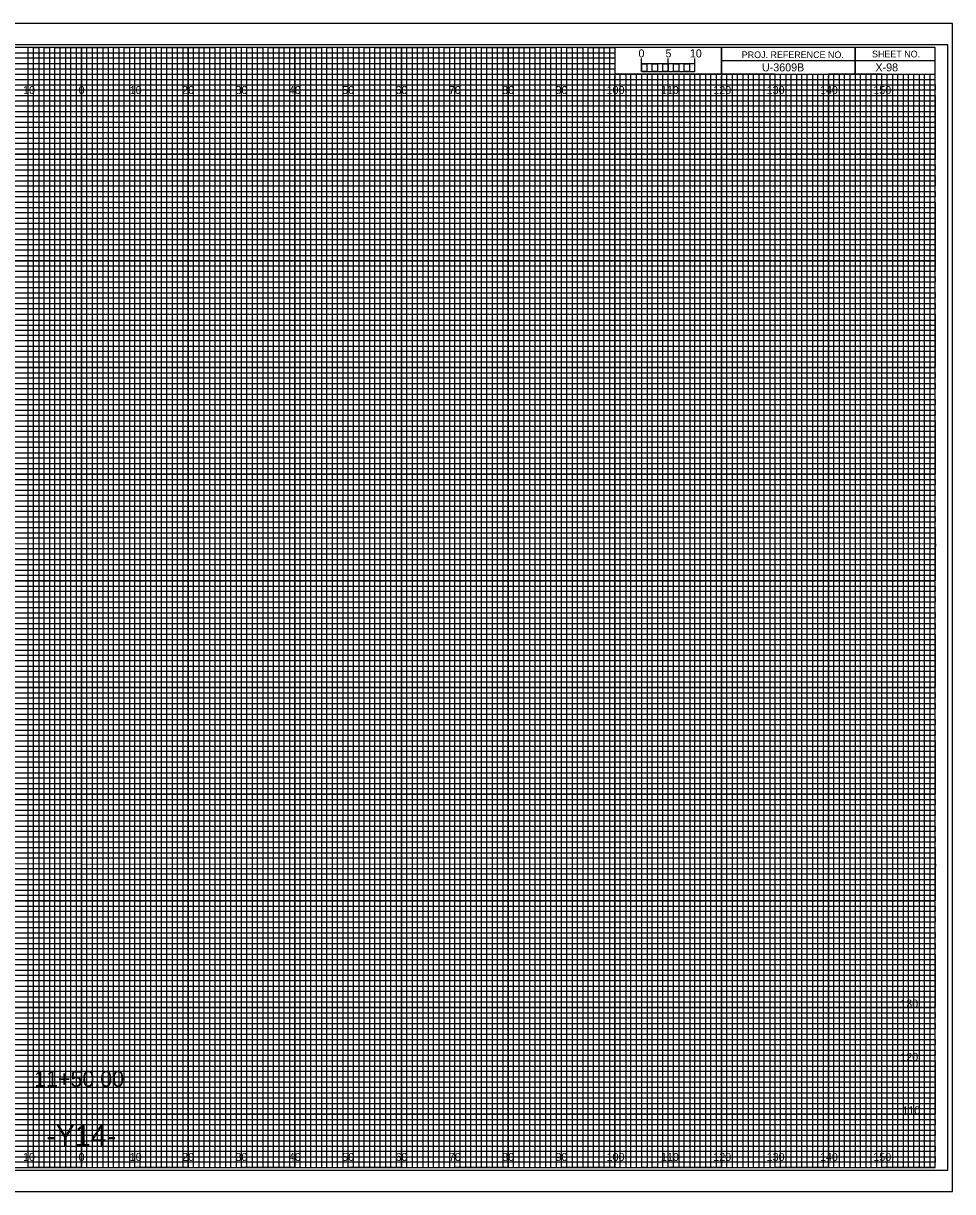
# Model space of a CAD drawing. Extents: x -13 to 323, y -5 to 434.
# Drawn here: x 149.1 to 323.3, y 215.5 to 434.5 of the extents above; entities that cross this region are included whole.
import ezdxf

# ---------------------------------------------------------------- set-up
doc = ezdxf.new("R2010")
doc.units = 0
for name, color, linetype in [('Prop XS Alignment Label', 7, 'Continuous'), ('Prop XS Bar Scale Labels', 7, 'Continuous'), ('Prop XS Elevation Labels', 7, 'Continuous'), ('Prop XS Offset Labels', 7, 'Continuous'), ('Prop XS Project Number', 7, 'Continuous'), ('Prop XS Sheet Number', 7, 'Continuous'), ('Prop XS Station Labels', 7, 'Continuous'), ('Sheet Cross Section CELL', 7, 'Continuous'), ('Sheet Cross Section Grid Major CELL', 7, 'Continuous'), ('Sheet Cross Section Grid Middle CELL', 7, 'Continuous'), ('Sheet Cross Section Grid Minor 1 CELL', 7, 'Continuous'), ('Sheet Cross Section Grid Minor 2 CELL', 7, 'Continuous'), ('Sheet Cross Section Scale CELL', 7, 'Continuous'), ('Sheet Cutting Line CELL', 7, 'Continuous'), ('Sheet DOT Grid CELL', 7, 'Continuous'), ('Sheet Plot Border Inside CELL', 7, 'Continuous'), ('Sheet Plot Border Outside CELL', 7, 'Continuous')]:
    doc.layers.add(name, color=color, linetype=linetype)

msp = doc.modelspace()

# ---------------------------------------------------------------- linework, layer by layer
at = {"layer": 'Sheet Cross Section CELL'}
for p, q in [((305, 430), (305, 425)), ((305, 425), (305, 430)), ((280, 427.5), (280, 425)), ((320, 427.49), (280, 427.49)), ((280, 425), (320, 425))]:
    msp.add_line(p, q, dxfattribs=at)
for points in [[(320, 430), (0, 430), (0, 220), (320, 220)], [(280, 430), (260, 430), (260, 425.03), (280, 425.03)], [(320, 430), (280, 430), (280, 425), (320, 425)]]:
    msp.add_lwpolyline(points, close=True, dxfattribs=at)
at = {"layer": 'Sheet Cross Section Grid Major CELL'}
for p, q in [((150, 430), (140, 430)), ((150, 220), (150, 430)), ((170, 430), (160, 430)), ((160, 430), (160, 220)), ((170, 220), (170, 430)), ((190, 430), (180, 430)), ((180, 430), (180, 220)), ((190, 220), (190, 430)), ((210, 430), (200, 430)), ((200, 430), (200, 220)), ((210, 220), (210, 430)), ((230, 430), (220, 430)), ((220, 430), (220, 220)), ((230, 220), (230, 430)), ((250, 430), (240, 430)), ((240, 430), (240, 220)), ((250, 220), (250, 430)), ((260, 430), (260, 220)), ((270, 220), (270, 425)), ((290, 425), (280, 425)), ((280, 425), (280, 220)), ((290, 220), (290, 425)), ((310, 425), (300, 425)), ((300, 425), (300, 220)), ((310, 220), (310, 425)), ((160, 220), (150, 220)), ((180, 220), (170, 220)), ((200, 220), (190, 220)), ((220, 220), (210, 220)), ((240, 220), (230, 220)), ((260, 220), (250, 220)), ((280, 220), (270, 220)), ((300, 220), (290, 220)), ((320, 220), (310, 220)), ((320, 220), (320, 220))]:
    msp.add_line(p, q, dxfattribs=at)
for points in [[(0, 420), (320, 420), (320, 410), (0, 410)], [(0, 400), (320, 400), (320, 390), (0, 390)], [(0, 380), (320, 380), (320, 370), (0, 370)], [(0, 360), (320, 360), (320, 350), (0, 350)], [(0, 340), (320, 340), (320, 330), (0, 330)], [(0, 320), (320, 320), (320, 310), (0, 310)], [(0, 300), (320, 300), (320, 290), (0, 290)], [(0, 280), (320, 280), (320, 270), (0, 270)], [(0, 260), (320, 260), (320, 250), (0, 250)], [(0, 240), (320, 240), (320, 230), (0, 230)]]:
    msp.add_lwpolyline(points, dxfattribs=at)
at = {"layer": 'Sheet Cross Section Grid Middle CELL'}
for points in [[(145, 220), (155, 220), (155, 430), (165, 430), (165, 220), (175, 220), (175, 430), (185, 430), (185, 220), (195, 220), (195, 430), (205, 430), (205, 220), (215, 220), (215, 430), (225, 430), (225, 220), (235, 220), (235, 430), (245, 430), (245, 220), (255, 220), (255, 430), (259.93, 430), (260, 430), (260, 425), (264.99, 425), (264.99, 220), (275, 220), (275, 425), (285, 425), (285, 220), (295, 220), (295, 425), (305, 425), (305, 220), (315, 220), (315, 425)], [(0, 425), (275, 425)], [(0, 405), (320, 405), (320, 415), (0, 415)], [(0, 385), (320, 385), (320, 395), (0, 395)], [(0, 365), (320, 365), (320, 375), (0, 375)], [(0, 345), (320, 345), (320, 355), (0, 355)], [(0, 325), (320, 325), (320, 335), (0, 335)], [(0, 305), (320, 305), (320, 315), (0, 315)], [(0, 285), (320, 285), (320, 295), (0, 295)], [(0, 265), (320, 265), (320, 275), (0, 275)], [(0, 245), (320, 245), (320, 255), (0, 255)], [(0, 225), (320, 225), (320, 235), (0, 235)]]:
    msp.add_lwpolyline(points, dxfattribs=at)
at = {"layer": 'Sheet Cross Section Grid Minor 1 CELL'}
for p, q in [((0, 429), (260, 429)), ((260, 427.98), (0, 427.98)), ((260, 429), (260, 427.98)), ((0, 427), (260, 427)), ((260, 425.89), (0, 425.89)), ((260, 427), (260, 425.89)), ((0, 424), (320, 424))]:
    msp.add_line(p, q, dxfattribs=at)
for points in [[(0, 423), (270, 423), (320, 423), (320, 422), (0, 422)], [(0, 421), (320, 421), (320, 419), (0, 419)], [(0, 418), (320, 418), (320, 417), (0, 416.98)], [(0, 416), (320, 416), (320, 414), (0, 414)], [(0, 413), (320, 413), (320, 412), (0, 412)], [(0, 411), (320, 411), (320, 409), (0, 409)], [(0, 408), (320, 408), (320, 407), (0, 407)], [(0, 406), (320, 406), (320, 404), (0, 404)], [(0, 403), (320, 403), (320, 402), (0, 402)], [(0, 401), (320, 401), (320, 399), (0, 399)], [(0, 398), (320, 398), (320, 397), (0, 397)], [(0, 396), (320, 396), (320, 393.95), (320, 393), (320, 392), (0, 392)], [(0, 394), (320, 394), (320, 393), (0, 393)], [(0, 391), (320, 391), (320, 389), (0, 389.03)], [(0, 389.03), (320, 389), (320, 388), (0, 388)], [(0, 387), (320, 387), (320, 386), (0, 386)], [(0, 384), (320, 384), (320, 383), (0, 383)], [(0, 382), (320, 382), (320, 381), (0, 381)], [(-0.07, 378.89), (320, 378.89), (320, 377.88), (-0.07, 377.88)], [(0, 377), (320, 377), (320, 376), (0, 376)], [(0, 374), (320, 374), (320, 373), (0, 373)], [(0, 372), (320, 372), (320, 371), (0, 371)], [(0, 369), (320, 369), (320, 368), (0, 368)], [(0, 367), (320, 367), (320, 366), (0, 366)], [(0, 364), (320, 364), (320, 363), (0, 363)], [(0, 362), (320, 362), (320, 361), (0, 361)], [(0, 359), (320, 359), (319.99, 357.98), (0, 358)], [(0, 357), (320, 357), (320, 356), (0, 356)], [(0, 354), (320, 354), (320, 353), (0, 353)], [(0, 352), (320, 352), (320, 351), (0, 351)], [(0, 349), (320, 349), (320, 348), (0, 348)], [(0, 347), (320, 347), (320, 346), (0, 346)], [(0, 344), (320, 344), (320, 343), (0, 343)], [(0, 342), (320, 342), (320, 341), (0, 341)], [(0, 339), (320, 339), (320, 338), (0, 338)], [(0, 336.99), (320.07, 336.91), (320, 336), (0, 336)], [(0, 334), (320, 334), (320, 333), (0, 333)], [(0, 332), (320, 332), (320, 331), (0, 331)], [(0, 329), (320, 329), (320, 328), (0, 328)], [(0, 327), (320, 327), (320, 326), (0, 326)], [(0, 324), (320, 324), (320, 323), (0, 323)], [(0, 322), (320, 322), (320, 321), (0, 321)], [(0, 319), (320, 319), (320, 318), (0, 318)], [(0, 317), (320, 317), (320, 316), (0, 316)], [(0, 314), (320, 314), (320, 313), (0, 313)], [(0, 312), (320, 312), (320, 311), (0, 311)], [(0, 309), (320, 309), (320, 308), (0, 308)], [(0, 307), (320, 307), (320, 306), (0, 306)], [(0, 304), (320, 304), (320, 303), (0, 303)], [(0, 302), (320, 302), (320, 301), (0, 301)], [(0, 299), (320, 299), (319.99, 297.98), (0, 298)], [(0, 297), (320, 297), (320, 296), (0, 296)], [(0, 294), (320, 294), (320, 293), (0, 293)], [(0, 292), (320, 292), (320, 291), (0, 291)], [(0, 289), (320, 289), (320, 288), (0, 288)], [(0, 287), (320, 287), (320, 286), (0, 286)], [(0, 284), (320, 284), (320, 283), (0, 283)], [(0, 282), (320, 282), (320, 281), (0, 281)], [(0, 279), (320, 279), (320, 278), (0, 278)], [(0, 276.99), (320.07, 276.91), (320, 276), (0, 276)], [(0, 274), (320, 274), (320, 273), (0, 273)], [(0, 272), (320, 272), (320, 271), (0, 271)], [(0, 269), (320, 269), (320, 268), (0, 268)], [(0, 267), (320, 267), (320, 266), (0, 266)], [(0, 264), (320, 264), (320, 263), (0, 263)], [(0, 262), (320, 262), (320, 261), (0, 261)], [(0, 259), (320, 259), (320, 258), (0, 258)], [(0, 257), (320, 257), (320, 256), (0, 256)], [(0, 254), (320, 254), (320, 253), (0, 253)], [(0, 252), (320, 252), (320, 251), (0, 251)], [(0, 249), (320, 249), (320, 248), (0, 248)], [(0, 247), (320, 247), (320, 246), (0, 246)], [(0, 244), (320, 244), (320, 243), (0, 243)], [(0, 242), (320, 242), (320, 241), (0, 241)], [(0, 239), (320, 239), (320, 238), (0, 238)], [(0, 237), (320, 237), (320, 236), (0, 236)], [(0, 234), (320, 234), (320, 233), (0, 233)], [(0, 232), (320, 232), (320, 231), (0, 231)], [(0, 229), (320, 229), (320, 228), (0, 228)], [(0, 227), (320, 227), (320, 226), (0, 226)], [(0, 224), (320, 224), (320, 223), (0, 223)], [(0, 222), (320, 222), (320, 221), (0, 221)]]:
    msp.add_lwpolyline(points, dxfattribs=at)
at = {"layer": 'Sheet Cross Section Grid Minor 2 CELL'}
for p, q in [((267, 425), (266.01, 425)), ((266.01, 425), (266.01, 220)), ((267, 220), (267, 425)), ((269, 425), (268, 425)), ((268, 425), (268, 220)), ((269, 220), (269, 425)), ((266.01, 220), (265, 220)), ((268, 220), (267, 220))]:
    msp.add_line(p, q, dxfattribs=at)
for points in [[(150, 220), (151, 220), (151, 430), (152, 430), (152, 220)], [(152, 220), (153, 220), (153, 430), (154, 430), (154, 220)], [(155, 220), (156, 220), (156, 430), (157, 430), (157, 220)], [(157, 220), (158, 220), (158, 430), (159, 430), (159, 220)], [(160, 220), (161, 220), (161, 430), (162, 430), (162, 220)], [(162, 220), (163, 220), (163, 430), (164, 430), (164, 220)], [(165, 220), (166, 220), (166, 430), (167, 430), (167, 220)], [(167, 220), (168, 220), (168, 430), (169, 430), (169, 220)], [(170, 220), (171, 220), (171, 430), (172, 430), (172, 220)], [(172, 220), (173, 220), (173, 430), (174, 430), (174, 220)], [(175, 220), (176, 220), (176, 430), (177, 430), (177, 220)], [(177, 220), (178, 220), (178, 430), (179, 430), (179, 220)], [(180, 220), (181, 220), (181, 430), (182, 430), (182, 220)], [(182, 220), (183, 220), (183, 430), (184, 430), (184, 220)], [(185, 220), (186, 220), (186, 430), (187, 430), (187, 220)], [(187, 220), (188, 220), (188, 430), (189, 430), (189, 220)], [(190, 220), (191, 220), (191, 430), (192, 430), (192, 220)], [(192, 220), (193, 220), (193, 430), (194, 430), (194, 220)], [(195, 220), (196, 220), (196, 430), (197, 430), (197, 220)], [(197, 220), (198, 220), (198, 430), (199, 430), (199, 220)], [(200, 220), (201, 220), (201, 430), (202, 430), (202, 220)], [(202, 220), (203, 220), (203, 430), (204, 430), (204, 220)], [(205, 220), (206, 220), (206, 430), (207, 430), (207, 220)], [(207, 220), (208, 220), (208, 430), (209, 430), (209, 220)], [(210, 220), (211, 220), (211, 430), (212, 430), (212, 220)], [(212, 220), (213, 220), (213, 430), (214, 430), (214, 220)], [(215, 220), (216, 220), (216, 430), (217, 430), (217, 220)], [(217, 220), (218, 220), (218, 430), (219, 430), (219, 220)], [(220, 220), (221, 220), (221, 430), (222, 430), (222, 220)], [(222, 220), (223, 220), (223, 430), (224, 430), (224, 220)], [(225, 220), (226, 220), (226, 430), (227, 430), (227, 220)], [(227, 220), (228, 220), (228, 430), (229, 430), (229, 220)], [(230, 220), (231, 220), (231, 430), (232, 430), (232, 220)], [(232, 220), (233, 220), (233, 430), (234, 430), (234, 220)], [(235, 220), (236, 220), (236, 430), (237, 430), (237, 220)], [(237, 220), (238, 220), (238, 430), (239, 430), (239, 220)], [(240, 220), (241, 220), (241, 430), (242, 430), (242, 220)], [(242, 220), (243, 220), (243, 430), (244, 430), (244, 220)], [(245, 220), (246, 220), (246, 430), (247, 430), (247, 220)], [(247, 220), (248, 220), (248, 430), (249, 430), (249, 220)], [(250, 220), (251, 220), (251, 430), (252, 430), (252, 220)], [(252, 220), (253, 220), (253, 430), (254, 430), (254, 220)], [(255, 220), (256, 220), (256, 430), (257, 430), (257, 220)], [(257, 220), (258, 220), (258, 430), (259, 430), (259, 220)], [(260, 220), (261, 220), (261, 425), (262.02, 425), (262.02, 220)], [(262, 220), (263, 220), (263, 425), (263.99, 425), (263.99, 220)], [(270, 220), (270.98, 220), (270.98, 425), (272, 425), (272, 220)], [(272, 220), (273, 220), (273, 425), (274.05, 425), (274.05, 220)], [(275, 220), (276, 220), (276, 425), (277, 425), (277, 220)], [(277, 220), (278, 220), (278, 425), (279, 425), (279, 220)], [(280, 220), (281, 220), (281, 425), (282, 425), (282, 220)], [(282, 220), (283, 220), (283, 425), (284, 425), (284, 220)], [(285, 220), (286, 220), (286, 425), (287, 425), (287, 220)], [(287, 220), (288, 220), (288, 425), (289, 425), (289, 220)], [(290, 220), (291, 220), (291, 425), (292, 425), (292, 220)], [(292, 220), (293, 220), (293, 425), (294, 425), (294, 220)], [(295, 220), (296, 220), (296, 425), (297, 425), (297, 220)], [(297, 220), (298, 220), (298, 425), (299, 425), (299, 220)], [(300, 220), (301, 220), (301, 425), (302, 425), (302, 220)], [(302, 220), (303, 220), (303, 425), (304, 425), (304, 220)], [(305, 220), (306, 220), (306, 425), (307, 425), (307, 220)], [(307, 220), (308, 220), (308, 425), (309, 425), (309, 220)], [(310, 220), (311, 220), (311, 425), (312, 425), (312, 220)], [(312, 220), (313, 220), (313, 425), (314, 425), (314, 220)], [(315, 220), (316, 220), (316, 425), (317, 425), (317, 220)], [(317, 220), (318, 220), (318, 425), (319, 425), (319, 220)]]:
    msp.add_lwpolyline(points, dxfattribs=at)
at = {"layer": 'Sheet Cross Section Scale CELL'}
for p, q in [((265, 425.49), (265, 427.9)), ((265, 426.9), (265, 427.9)), ((270, 425.49), (270, 427.9)), ((275, 425.49), (275, 427.9)), ((275, 426.9), (275, 427.9))]:
    msp.add_line(p, q, dxfattribs=at)
for points in [[(275, 426.9), (265, 426.9), (265, 425.49), (275, 425.49)], [(265, 426.9), (266, 426.9), (266, 425.49), (265, 425.49)], [(267, 426.9), (268, 426.9), (268, 425.49), (267, 425.49)], [(269, 426.9), (270, 426.9), (270, 425.49), (269, 425.49)], [(271, 426.9), (272, 426.9), (272, 425.49), (271, 425.49)], [(273, 426.9), (274, 426.9), (274, 425.49), (273, 425.49)]]:
    msp.add_lwpolyline(points, close=True, dxfattribs=at)
at = {"layer": 'Sheet Cutting Line CELL'}
for p, q in [((323.3, 434.5), (-13.4, 434.5)), ((-13.4, 215.5), (323.3, 215.5))]:
    msp.add_line(p, q, dxfattribs=at)
at = {"layer": 'Sheet DOT Grid CELL'}
for p, q in [((150, 220), (150, 430)), ((160, 220), (160, 430)), ((170, 220), (170, 430)), ((180, 220), (180, 430)), ((190, 220), (190, 430)), ((200, 220), (200, 430)), ((210, 220), (210, 430)), ((220, 220), (220, 430)), ((230, 220), (230, 430)), ((240, 220), (240, 430)), ((250, 220), (250, 430)), ((260, 220), (260, 424.69)), ((270, 220), (270, 424.69)), ((280, 220), (280, 424.69)), ((290, 220), (290, 424.69)), ((300, 220), (300, 424.69)), ((310, 220), (310, 424.69)), ((0, 420), (320, 420)), ((0, 410), (320, 410)), ((0, 400), (320, 400)), ((0, 390), (320, 390)), ((0, 380), (320, 380)), ((0, 370), (320, 370)), ((0, 360), (320, 360)), ((0, 350), (320, 350)), ((0, 340), (320, 340)), ((0, 330), (320, 330)), ((0, 320), (320, 320)), ((0, 310), (320, 310)), ((0, 300), (320, 300)), ((0, 290), (320, 290)), ((0, 280), (320, 280)), ((0, 270), (320, 270)), ((0, 260), (320, 260)), ((0, 250), (320, 250)), ((0, 240), (320, 240)), ((0, 230), (320, 230))]:
    msp.add_line(p, q, dxfattribs=at)
at = {"layer": 'Sheet Plot Border Inside CELL'}
msp.add_lwpolyline([(-10.8, 219.5), (322.4, 219.5), (322.4, 430.5), (-10.8, 430.5)], close=True, dxfattribs=at)
at = {"layer": 'Sheet Plot Border Outside CELL'}
msp.add_lwpolyline([(-13.4, 215.5), (323.3, 215.5), (323.3, 434.5), (-13.4, 434.5)], close=True, dxfattribs=at)

# ---------------------------------------------------------------- texts
at = {"layer": 'Prop XS Alignment Label'}
msp.add_text('-Y14-', height=4, dxfattribs=at).set_placement((153.41, 224))
at = {"layer": 'Prop XS Bar Scale Labels'}
for s, p in [('5', (269.47, 428.12)), ('10', (274.04, 428.12))]:
    msp.add_text(s, height=1.5, dxfattribs=at).set_placement(p)
at = {"layer": 'Prop XS Elevation Labels'}
for s, p in [('130', (313.49, 250)), ('120', (313.5, 240)), ('110', (313.88, 230))]:
    msp.add_text(s, height=1.5, dxfattribs=at).set_placement(p)
at = {"layer": 'Prop XS Offset Labels'}
for s, p in [('10', (149.04, 421.25)), ('0', (159.45, 421.25)), ('0', (159.45, 421.25)), ('10', (169.04, 421.25)), ('20', (178.86, 421.25)), ('30', (188.86, 421.25)), ('40', (198.86, 421.25)), ('50', (208.86, 421.25)), ('60', (218.86, 421.25)), ('70', (228.86, 421.25)), ('80', (238.86, 421.25)), ('90', (248.86, 421.25)), ('100', (258.44, 421.25)), ('110', (268.62, 421.25)), ('120', (278.44, 421.25)), ('130', (288.44, 421.25)), ('140', (298.44, 421.25)), ('150', (308.44, 421.25)), ('10', (149.04, 221.25)), ('0', (159.45, 221.25)), ('0', (159.45, 221.25)), ('10', (169.04, 221.25)), ('20', (178.86, 221.25)), ('30', (188.86, 221.25)), ('40', (198.86, 221.25)), ('50', (208.86, 221.25)), ('60', (218.86, 221.25)), ('70', (228.86, 221.25)), ('80', (238.86, 221.25)), ('90', (248.86, 221.25)), ('100', (258.44, 221.25)), ('110', (268.62, 221.25)), ('120', (278.44, 221.25)), ('130', (288.44, 221.25)), ('140', (298.44, 221.25)), ('150', (308.44, 221.25))]:
    msp.add_text(s, height=1.5, dxfattribs=at).set_placement(p)
at = {"layer": 'Prop XS Project Number'}
msp.add_text('U-3609B', height=1.5, dxfattribs=at).set_placement((287.56, 425.5))
at = {"layer": 'Prop XS Sheet Number'}
msp.add_text('X-98', height=1.5, dxfattribs=at).set_placement((308.83, 425.5))
at = {"layer": 'Prop XS Station Labels'}
msp.add_text('11+50.00', height=3, dxfattribs=at).set_placement((151.13, 235.15))
at = {"layer": 'Sheet Cross Section CELL'}
for s, p in [('PROJ. REFERENCE NO.', (283.77, 427.99)), ('SHEET NO.', (308.19, 428.12))]:
    msp.add_text(s, height=1.25, dxfattribs=at).set_placement(p)
at = {"layer": 'Sheet Cross Section Scale CELL'}
msp.add_text('0', height=1.5, dxfattribs=at).set_placement((264.41, 428.12))

doc.saveas('drawing.dxf')
